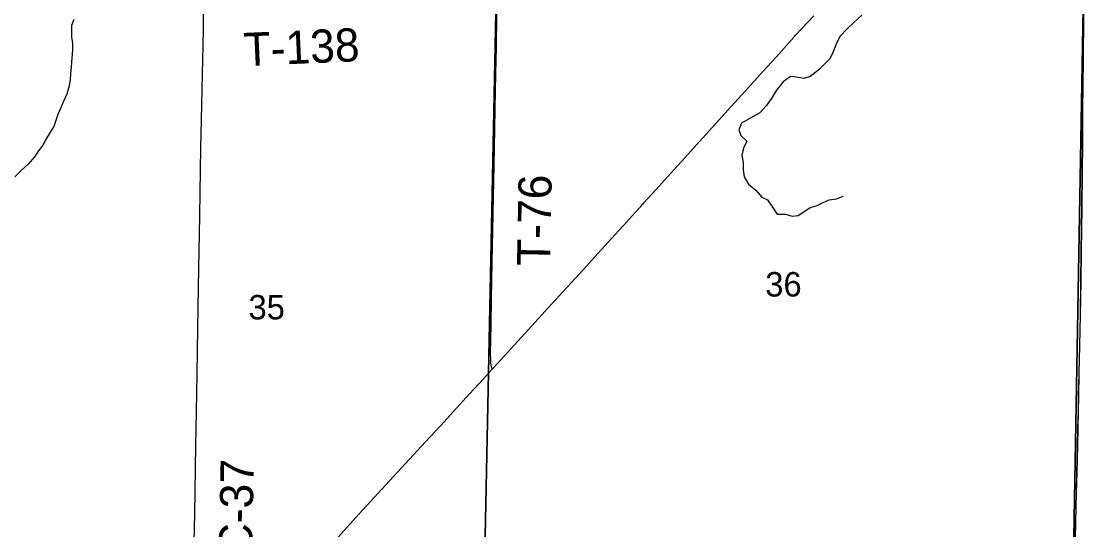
# Model space of a CAD drawing. Extents: x 0 to 34, y 0 to 22.
# Drawn here: x 5.839 to 6.761, y 17.804 to 18.239 of the extents above; entities that cross this region are included whole.
import ezdxf

# ---------------------------------------------------------------- set-up
doc = ezdxf.new("R2010")
doc.units = 0
for name, color, linetype in [('GM_X_Corporation', 7, 'Continuous'), ('GM_X_County_Road', 7, 'Continuous'), ('GM_X_County_Road_Text', 7, 'Continuous'), ('GM_X_Minor_River', 7, 'Continuous'), ('GM_X_Section_Text', 7, 'Continuous'), ('GM_X_State_Route', 7, 'Continuous'), ('GM_X_Township_Road', 7, 'Continuous'), ('GM_X_Township_Road_Text', 7, 'Continuous')]:
    doc.layers.add(name, color=color, linetype=linetype)

msp = doc.modelspace()

# ---------------------------------------------------------------- linework, layer by layer
at = {"layer": 'GM_X_Corporation'}
for points in [[(6.74808, 18.28309), (7.28799, 18.29396), (7.29091, 17.78707), (7.27632, 17.78697), (6.73948, 17.78158)], [(6.24542, 18.26006), (6.74808, 18.28309), (6.73948, 17.78158), (6.23511, 17.75666)], [(5.74338, 18.24402), (6.24542, 18.26006), (6.23511, 17.75666), (6.21312, 17.75585), (5.73364, 17.74138), (5.73061, 17.74103), (5.74922, 17.99349)]]:
    msp.add_lwpolyline(points, close=True, dxfattribs=at)
msp.add_lwpolyline([(6.74796, 18.24347), (6.74765, 18.20588), (6.74719, 18.16277), (6.74702, 18.13514), (6.74666, 18.10965), (6.74647, 18.07949), (6.74622, 18.06153), (6.74595, 18.04188), (6.74562, 18.01608), (6.7451, 17.98785), (6.74455, 17.96169), (6.74406, 17.93873), (6.74364, 17.91797), (6.74346, 17.90602), (6.74304, 17.89105), (6.7427, 17.87582), (6.74218, 17.8533), (6.74177, 17.83586), (6.74117, 17.81103), (6.74072, 17.79647)], dxfattribs=at)
msp.add_lwpolyline([(6.74796, 18.24347), (6.74765, 18.20588), (6.74719, 18.16277), (6.74702, 18.13514), (6.74666, 18.10965), (6.74647, 18.07949), (6.74622, 18.06153), (6.74595, 18.04188), (6.74562, 18.01608), (6.7451, 17.98785), (6.74455, 17.96169), (6.74406, 17.93873), (6.74364, 17.91797), (6.74346, 17.90602), (6.74304, 17.89105), (6.7427, 17.87582), (6.74218, 17.8533), (6.74177, 17.83586), (6.74117, 17.81103), (6.74072, 17.79647)], dxfattribs=at)
at = {"layer": 'GM_X_County_Road'}
msp.add_lwpolyline([(5.98599, 17.74638), (5.98713, 17.79325), (5.98759, 17.81811), (5.98789, 17.83675), (5.98869, 17.87653), (5.98908, 17.90543), (5.9894, 17.92096), (5.98961, 17.93743), (5.99038, 17.97689), (5.99121, 18.02785), (5.99204, 18.0726), (5.99287, 18.13102), (5.99341, 18.15432), (5.99429, 18.1944), (5.99447, 18.2056), (5.99483, 18.21833), (5.99506, 18.2323), (5.99514, 18.24443), (5.9952, 18.24792)], dxfattribs=at)
at = {"layer": 'GM_X_Minor_River'}
for points in [[(6.55825, 18.24421), (6.5514, 18.2378), (6.54589, 18.2329), (6.53942, 18.22593), (6.53635, 18.21931), (6.53347, 18.21231), (6.53098, 18.20682), (6.52146, 18.1974), (6.51405, 18.19175), (6.50875, 18.19008), (6.50232, 18.19106), (6.49722, 18.19166), (6.49095, 18.18733), (6.48542, 18.17997), (6.48122, 18.17355), (6.47664, 18.16694), (6.47093, 18.16072), (6.46599, 18.15771), (6.46125, 18.15527), (6.45536, 18.15189), (6.45306, 18.14622), (6.45492, 18.14128), (6.46, 18.13651), (6.45713, 18.13046), (6.45558, 18.1244), (6.45667, 18.11795), (6.45664, 18.11188), (6.45774, 18.106), (6.46148, 18.09972), (6.4677, 18.09457), (6.47277, 18.08866), (6.47767, 18.08636), (6.4818, 18.08008), (6.48592, 18.07418), (6.49311, 18.07395), (6.49859, 18.0724), (6.50389, 18.07294), (6.50882, 18.07594), (6.51414, 18.07971), (6.52021, 18.08138), (6.52514, 18.08401), (6.53045, 18.08625), (6.53651, 18.08716), (6.5422, 18.08941)], [(5.88422, 18.24041), (5.8823, 18.2353), (5.88208, 18.23056), (5.88224, 18.22544), (5.88296, 18.22013), (5.88293, 18.21539), (5.88272, 18.21047), (5.8823, 18.2044), (5.88189, 18.19947), (5.88148, 18.19398), (5.88107, 18.18924), (5.8801, 18.18375), (5.87816, 18.17656), (5.8751, 18.16994), (5.87279, 18.16426), (5.87049, 18.15916), (5.86895, 18.15405), (5.86721, 18.14894), (5.86397, 18.14403), (5.86015, 18.13798), (5.85766, 18.13307), (5.85404, 18.12816), (5.8506, 18.12306), (5.84508, 18.11683), (5.83956, 18.11174), (5.83386, 18.10609)]]:
    msp.add_lwpolyline(points, dxfattribs=at)
at = {"layer": 'GM_X_State_Route'}
msp.add_lwpolyline([(6.11021, 17.79797), (6.12808, 17.81743), (6.15435, 17.84605), (6.1851, 17.87942), (6.19777, 17.89311), (6.20865, 17.90507), (6.2227, 17.92043), (6.23428, 17.933), (6.24212, 17.94151), (6.2465, 17.94627), (6.27295, 17.97515), (6.29297, 17.99728), (6.32304, 18.03), (6.33251, 18.0403), (6.34718, 18.05679), (6.35034, 18.06021), (6.35445, 18.06442), (6.36475, 18.07566), (6.36911, 18.08052), (6.37195, 18.08381), (6.38198, 18.09485), (6.39992, 18.11466), (6.40433, 18.11947), (6.41684, 18.1333), (6.44651, 18.16597), (6.46143, 18.18223), (6.47381, 18.19618), (6.48491, 18.20835), (6.50048, 18.22568), (6.50192, 18.22728), (6.51716, 18.24364)], dxfattribs=at)
at = {"layer": 'GM_X_Township_Road'}
for points in [[(6.74038, 17.78184), (6.74045, 17.78427), (6.74083, 17.79619), (6.74129, 17.81075), (6.74188, 17.83559), (6.74229, 17.85303), (6.74281, 17.87554), (6.74315, 17.89077), (6.74357, 17.90575), (6.74375, 17.91769), (6.74417, 17.93846), (6.74466, 17.96141), (6.74521, 17.98757), (6.74573, 18.01581), (6.74606, 18.04161), (6.74633, 18.06126), (6.74658, 18.07922), (6.74677, 18.10937), (6.74713, 18.13486), (6.7473, 18.1625), (6.74776, 18.2056), (6.74807, 18.2432), (6.74843, 18.27335), (6.74846, 18.28308)], [(6.24212, 17.94151), (6.24156, 17.94372), (6.24124, 17.94503), (6.24099, 17.9466), (6.24087, 17.94888), (6.24078, 17.95569), (6.24087, 17.96656), (6.24111, 17.9796), (6.24162, 18.00197), (6.24219, 18.03274), (6.24265, 18.06039), (6.24323, 18.08866), (6.2437, 18.11632), (6.24439, 18.14678), (6.24461, 18.16448), (6.24526, 18.194), (6.24569, 18.217), (6.24608, 18.24342), (6.24627, 18.25928)]]:
    msp.add_lwpolyline(points, dxfattribs=at)

# ---------------------------------------------------------------- texts
at = {"layer": 'GM_X_County_Road_Text'}
msp.add_text('C-37', height=0.028409, rotation=88.97145, dxfattribs=at).set_placement((6.03671, 17.78213))
at = {"layer": 'GM_X_Section_Text'}
for s, p in [('36', (6.47568, 18.00362)), ('35', (6.0336, 17.98404))]:
    msp.add_text(s, height=0.020928, rotation=0.00001, dxfattribs=at).set_placement(p)
at = {"layer": 'GM_X_Township_Road_Text'}
for s, rotation, p in [('T-138', 2.53131, (6.02999, 18.20057)), ('T-76', 88.95187, (6.29166, 18.02953))]:
    msp.add_text(s, height=0.028409, rotation=rotation, dxfattribs=at).set_placement(p)

doc.saveas('drawing.dxf')
